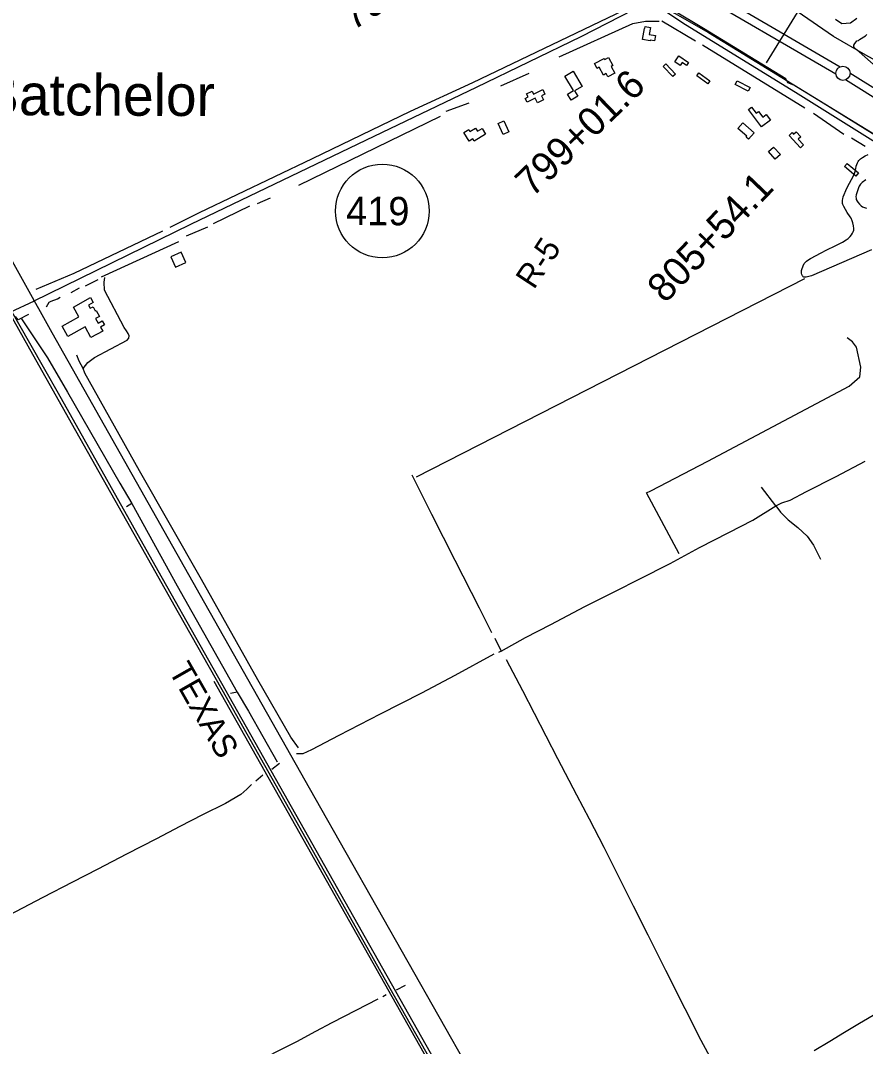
# Model space of a CAD drawing. Extents: x 3161514 to 3199414, y 831166 to 856601.
# Drawn here: x 3177957 to 3180931, y 848812 to 852425 of the extents above; entities that cross this region are included whole.
import ezdxf

# ---------------------------------------------------------------- set-up
doc = ezdxf.new("R2010")
doc.units = 0
for name, color, linetype in [('V-BLDG-OTLN', 7, 'Continuous'), ('V-LEVE-TOET', 7, 'Continuous'), ('V-RAIL-IDEN', 7, 'Continuous'), ('V-RAIL-TRAK', 7, 'Continuous'), ('V-RIVR-RANG-IDEN', 7, 'Continuous'), ('V-ROAD-CNTR', 7, 'Continuous'), ('V-ROAD-IDEN', 7, 'Continuous'), ('V-SITE-VEGE', 7, 'Continuous'), ('V-SURV-IDEN', 7, 'Continuous'), ('V-SURV-LINE', 7, 'Continuous'), ('V-TOPO-GNAM-IDEN', 7, 'Continuous'), ('V-TOPO-SHOR', 7, 'Continuous'), ('V-UTIL-LINE', 7, 'Continuous')]:
    doc.layers.add(name, color=color, linetype=linetype)

msp = doc.modelspace()

# ---------------------------------------------------------------- linework, layer by layer
at = {"layer": 'V-BLDG-OTLN'}
for points in [[(3180146.2, 852357.6), (3180152.6, 852397.3), (3180154.4, 852397.1), (3180155.5, 852403.9), (3180174, 852400.9), (3180169.9, 852375.6), (3180191.5, 852372.1), (3180188.5, 852353.4), (3180172.9, 852355.9), (3180172.5, 852353.4)], [(3180026.6, 852295), (3180041.5, 852266.3), (3180036.1, 852263.5), (3180048.7, 852239.3), (3180024, 852226.5), (3180018, 852238.2), (3180008, 852232.9), (3179993.6, 852260.4), (3179985.8, 852256.3), (3179976.6, 852274), (3180010.6, 852291.7), (3180012.7, 852287.8)], [(3180259.6, 852280.1), (3180274.2, 852301.1), (3180308.3, 852277.3), (3180300.5, 852266.1), (3180285, 852276.9), (3180278.2, 852267.1)], [(3180261.9, 852236.3), (3180252.2, 852227.3), (3180218.8, 852263.2), (3180228.5, 852272.3)], [(3179901.7, 852246.4), (3179933.1, 852193), (3179906.7, 852177.4), (3179918.1, 852158.1), (3179894.3, 852144.1), (3179881.6, 852165.7), (3179902.9, 852178.2), (3179872.8, 852229.4)], [(3180383.3, 852212.2), (3180375.9, 852202.2), (3180336.9, 852230.8), (3180344.2, 852240.8)], [(3179794.5, 852181.7), (3179802.3, 852166.2), (3179789.8, 852159.9), (3179797, 852145.6), (3179775.9, 852134.9), (3179767.7, 852151.2), (3179740, 852137.2), (3179733.1, 852150.9), (3179743.1, 852156), (3179737.7, 852166.8), (3179757.1, 852176.6), (3179762.7, 852165.6)], [(3180472.5, 852199.9), (3180479.3, 852212.9), (3180525, 852189.2), (3180518.2, 852176.2)], [(3180564.9, 852050.1), (3180518.6, 852111.7), (3180529.8, 852120.1), (3180545.8, 852098.7), (3180554.2, 852104.9), (3180569.3, 852084.9), (3180581.7, 852094.2), (3180596.8, 852074.1)], [(3179564.7, 852034.9), (3179581.3, 852045), (3179593.7, 852024.7), (3179553.7, 852000.3), (3179549, 852007.9), (3179535.9, 852000), (3179517.3, 852030.5), (3179534.5, 852041), (3179538.6, 852034.2), (3179557.9, 852046)], [(3179655.4, 852023.7), (3179638, 852062.8), (3179658.1, 852071.8), (3179675.5, 852032.7)], [(3180499.3, 852064.4), (3180539.1, 852029.4), (3180519.5, 852007.1), (3180511, 852014.6), (3180513.3, 852017.2), (3180482, 852044.8)], [(3180701.8, 851977), (3180662.2, 852020.2), (3180673.2, 852030.3), (3180677.7, 852025.3), (3180686.3, 852033.1), (3180702.8, 852015.1), (3180693.8, 852006.8), (3180712.3, 851986.7)], [(3180631.2, 851953.2), (3180613.4, 851937.1), (3180589.5, 851963.4), (3180607.3, 851979.6)], [(3180896.5, 851877), (3180856.9, 851910.4), (3180866.5, 851921.7), (3180906.1, 851888.3)], [(3178521.9, 851609.7), (3178485.4, 851593.4), (3178501.7, 851556.9), (3178538.2, 851573.2)], [(3178123.1, 851312.2), (3178102.6, 851349.2), (3178161.7, 851382.1), (3178143, 851415.9), (3178202.6, 851449.1), (3178212.2, 851431.7), (3178195.8, 851422.6), (3178201.9, 851411.7), (3178211.7, 851417.2), (3178219.8, 851402.8), (3178222.4, 851404.2), (3178234, 851383.3), (3178220.5, 851375.8), (3178229.4, 851359.7), (3178244.3, 851368), (3178252.5, 851353.2), (3178238.3, 851345.3), (3178245.9, 851331.6), (3178204.5, 851308.5), (3178183.7, 851345.9)]]:
    msp.add_lwpolyline(points, close=True, dxfattribs=at)
at = {"layer": 'V-LEVE-TOET'}
for points in [[(3180222.9, 852474.1), (3180225.4, 852472.2), (3180246, 852458.1), (3180261.2, 852449.3), (3180276.7, 852440.2), (3180378.3, 852382.9), (3180599.4, 852247.2), (3180781.4, 852135.7), (3180979.3, 852013.2)], [(3181272.1, 852116.2), (3181228.7, 852143.9), (3181064, 852230.7), (3180932, 852303.1), (3180817.6, 852369.1), (3180690.2, 852456.5), (3180643.2, 852490.5)]]:
    msp.add_lwpolyline(points, dxfattribs=at)
at = {"layer": 'V-RAIL-TRAK'}
msp.add_lwpolyline([(3179765, 848116.8), (3179728.2, 848182.9), (3179629.2, 848358.8), (3179423.1, 848723.5), (3179257.9, 849016.2), (3178929.8, 849600), (3178666.2, 850067.6), (3178513.1, 850338.6), (3178372, 850589.2), (3178150.9, 850980.6), (3177999.7, 851248.7), (3177917.5, 851395.3)], dxfattribs=at)
at = {"layer": 'V-ROAD-CNTR'}
for points in [[(3176113.1, 854794), (3176223.6, 854594.2), (3176701.4, 853750.7), (3177143.6, 852967.7), (3177688.4, 852004.2), (3178067, 851325.8), (3178604, 850374.6), (3178992.2, 849687.5), (3179538.6, 848724.8), (3179946.2, 848000.9), (3180424.9, 847143.9), (3180815.4, 846445.1), (3181367.5, 845470.9)], [(3177592.2, 854789.9), (3177971.4, 854316.2), (3178263.7, 853942.1), (3178396, 853775.7), (3178430.3, 853732.9), (3178457, 853704.8), (3178482.7, 853679.1), (3178527.4, 853641.6), (3178608, 853580.7), (3178927.2, 853358), (3179165.4, 853188.9), (3179528.5, 852937.7), (3180018.6, 852597.4), (3180287.5, 852417.1), (3180694.2, 852166.9), (3181125.4, 851896.4)], [(3176082.6, 854665.9), (3176267.3, 854340.9), (3176547.5, 853846.5), (3176830, 853348), (3177122.2, 852831.6), (3177540.4, 852086.9), (3177896.6, 851451.3), (3178089, 851112.6), (3178439.3, 850488.8), (3178766, 849911.1), (3179200, 849142.2), (3179692.7, 848269.2), (3179881.1, 847935.3), (3180257.6, 847259.5), (3180606, 846647.7), (3180852.5, 846213.2), (3181321, 845381)], [(3180170.3, 852495.6), (3180113.7, 852462.5), (3179929.1, 852368.1), (3179560.9, 852189.5), (3179173.1, 852003.7), (3178554.8, 851706.8), (3178001.4, 851435.4)], [(3180900.2, 852431.8), (3180877.8, 852415.9), (3180848, 852413.4), (3180825.4, 852428.5)], [(3178004.9, 851437.1), (3177919.3, 851396.5), (3177527.3, 851206.9), (3176975.4, 850941.8), (3176777.7, 850848.2), (3176154.2, 850545.1), (3175803.4, 850374.2), (3175245.4, 850104.3), (3174206.5, 849596.9)], [(3178636.8, 850098.4), (3179509.7, 848551), (3179761.1, 848112.3), (3179881.5, 847899.5), (3180304.8, 847141), (3180338, 847095.4), (3180383.2, 847039)]]:
    msp.add_lwpolyline(points, dxfattribs=at)
at = {"layer": 'V-ROAD-IDEN'}
msp.add_circle((3179230, 851754.1), 165, dxfattribs=at)
at = {"layer": 'V-SITE-VEGE'}
for points in [[(3180968.3, 852261.6), (3180909.1, 852315.1), (3180902.2, 852319.9), (3180894.9, 852325.7), (3180890.2, 852332.2), (3180889.3, 852335.6), (3180890.2, 852338.5), (3180893, 852344), (3180897.5, 852350.1), (3180900.8, 852353), (3180905.7, 852355), (3180909.4, 852357.9), (3180930.6, 852370.7), (3180935, 852376.2)], [(3180741, 851525.8), (3180721.8, 851521.8), (3180718, 851521.2), (3180714.2, 851521.5), (3180711.7, 851522.6), (3180709.8, 851524.2), (3180708.5, 851526), (3180707, 851530.3), (3180705.8, 851535.6), (3180705.3, 851540.9), (3180705.4, 851544.3), (3180706.3, 851548.8), (3180711.5, 851561.1), (3180715.5, 851568.9), (3180719.1, 851573.6), (3180723.4, 851577.7), (3180727.9, 851581.3), (3180737.5, 851587.4), (3180774.8, 851607.2), (3180792.1, 851615.9), (3180826.9, 851632.9), (3180849.8, 851644.9), (3180862.6, 851652.3), (3180866.4, 851654.8), (3180870, 851657.7), (3180876.6, 851664.3), (3180881.4, 851670.2), (3180885.4, 851676.6), (3180887.8, 851681.3), (3180889.8, 851686.8), (3180890.3, 851692.2), (3180889.1, 851702.5), (3180886.5, 851712.8), (3180884.1, 851719.6), (3180879.8, 851728.5), (3180876.6, 851733.8), (3180866.5, 851748.7), (3180860.1, 851759.2), (3180854.4, 851770), (3180851.3, 851777.3), (3180850.3, 851780.8), (3180849.8, 851784.4), (3180850, 851791.9), (3180850.8, 851797), (3180852.6, 851803.7), (3180855.6, 851812.3), (3180861.4, 851825.9), (3180868, 851839.1), (3180882.1, 851865.2), (3180890.6, 851882.9), (3180894.6, 851893.2), (3180896.8, 851902.6), (3180898.4, 851912.3), (3180900.1, 851918.5), (3180902.3, 851923.8), (3180905.2, 851928.7), (3180907.6, 851931.8), (3180913.5, 851937.6), (3180920.2, 851942.6), (3180929.7, 851948.4), (3180939.8, 851953.1)], [(3180931.7, 851864.3), (3180919.5, 851854.9), (3180916.3, 851851.9), (3180913.5, 851848.6), (3180908.8, 851841.3), (3180906.3, 851836), (3180903.4, 851828.7), (3180899.8, 851818.6), (3180897.9, 851811.6), (3180897.2, 851804.6), (3180897.4, 851800), (3180898.5, 851794.2), (3180901, 851788.6), (3180903.3, 851784.9), (3180909.3, 851777.9), (3180915.7, 851772.4), (3180920.5, 851769.4), (3180927.4, 851766.4), (3180934.7, 851764.5)], [(3180952.2, 851617.1), (3180882.1, 851586.4), (3180741, 851525.8)]]:
    msp.add_lwpolyline(points, dxfattribs=at)
at = {"layer": 'V-SURV-LINE'}
for points in [[(3180826.5, 852236.3), (3180297.5, 852545.4)], [(3180312.7, 852571.3), (3180841.6, 852262.2)], [(3180876.2, 852241.3), (3181733.3, 851705.6)], [(3181717.4, 851680.2), (3180860.3, 852215.9)]]:
    msp.add_lwpolyline(points, dxfattribs=at)
msp.add_circle((3180851.3, 852239.2), 25, dxfattribs=at)
at = {"layer": 'V-TOPO-SHOR'}
for p, q in [((3180332.9, 852351.8), (3180214, 852422.4)), ((3180717.5, 852115.9), (3180357.1, 852338.8)), ((3179646.9, 852194.9), (3179746.5, 852239.1)), ((3179454.4, 852106.3), (3179536.3, 852135.1)), ((3178936.5, 851845.2), (3179434.5, 852088.6)), ((3180747.2, 852099.2), (3180855, 852024.8)), ((3180881, 852011.8), (3180929.3, 851982.1)), ((3178790.4, 851781), (3178836.9, 851800.9)), ((3178635.5, 851710.2), (3178763.9, 851772.1)), ((3178540.5, 851667), (3178616.3, 851698.7)), ((3178241.7, 851522), (3178513.2, 851647)), ((3178185.4, 851490.7), (3178229.5, 851512.6)), ((3179350, 850817.6), (3180717.5, 851516.2)), ((3178134.2, 851467), (3178164.1, 851483.6)), ((3180614.9, 850715.4), (3180564.5, 850781.4)), ((3179625.6, 850250.2), (3179648.2, 850204.4)), ((3179648.2, 850204.4), (3179639.3, 850199.3)), ((3178868.1, 849809.1), (3178841.2, 849787.8)), ((3178809, 849768.1), (3178785, 849746.8)), ((3179310.8, 849026.6), (3179278.9, 849010.9)), ((3179243.2, 848993.8), (3179231.5, 848986.5))]:
    msp.add_line(p, q, dxfattribs=at)
for points in [[(3178697.5, 853498.4), (3178945.3, 853325.8), (3179452.2, 852967.3), (3179757.6, 852754.8), (3180091.8, 852515.8), (3180105.1, 852491.4), (3180096.2, 852475.9), (3180078.5, 852460.5), (3179547.3, 852205.9), (3179328.2, 852104.1), (3178983.4, 851938.3)], [(3180985, 852010), (3180678.5, 852197.6), (3180658, 852205.1), (3180650.6, 852219.9), (3180360.8, 852396.4), (3180253, 852461.5), (3180254.9, 852467), (3180262.3, 852470.7)], [(3179852.8, 852296.7), (3180111.7, 852414), (3180156, 852422.8), (3180193.6, 852422.8), (3180204.7, 852422.8)], [(3178983.4, 851938.3), (3178585.6, 851748.3), (3178481.5, 851696.4)], [(3178456.3, 851683.4), (3178143.7, 851534.2), (3178010.2, 851477.3)], [(3178177.4, 851199.2), (3178194, 851220.2), (3178217.2, 851237.9), (3178332.3, 851298.8), (3178337.8, 851306.5), (3178338.9, 851314.3), (3178335.6, 851323.1), (3178330.1, 851332), (3178321.2, 851344.2), (3178252.6, 851475.9), (3178251.5, 851503.5), (3178253.7, 851520.1)], [(3178047.9, 851417.2), (3178057.9, 851432.7), (3178064.5, 851437.1), (3178086.6, 851444.9), (3178096.6, 851450.4)], [(3177984.8, 851389.5), (3177948.3, 851370.7), (3177939.4, 851382.9)], [(3177960.5, 851374), (3178051.2, 851236.8), (3178122, 851116.2), (3178305.7, 850795.3), (3178347.8, 850724.5), (3178330.1, 850712.3)], [(3180275.3, 850546.4), (3180160.1, 850761.9), (3180175, 850769.3), (3180375.6, 850873.4), (3180873.6, 851137.2), (3180910.7, 851170.6), (3180914.4, 851204.1), (3180899.6, 851274.7), (3180884.7, 851293.3), (3180866.1, 851308.1)], [(3178935.4, 849863.5), (3178907.7, 849901.2), (3178791.5, 850103.7), (3178593.4, 850456.7), (3178375.4, 850839.6), (3178182.9, 851182.6), (3178177.4, 851199.2), (3178163, 851225.8), (3178155.2, 851246.8)], [(3180614.9, 850715.4), (3180636.4, 850726.6), (3180665.7, 850736.1), (3180722.8, 850766.2), (3180827.1, 850819.8), (3180929.5, 850873.4)], [(3179333.9, 850825.4), (3179403, 850686.2), (3179484.9, 850525.1), (3179570.9, 850356.7), (3179614.5, 850270.4)], [(3178347.8, 850724.5), (3178508.2, 850434.5), (3178719.6, 850059.4), (3178695.3, 850055)], [(3179648.2, 850204.4), (3179733.9, 850252.1), (3179823.7, 850298.6), (3179942.8, 850361.2), (3180050.4, 850415.6), (3180134.7, 850458.1), (3180243, 850513.2), (3180346.5, 850569.5), (3180450.3, 850622.2), (3180533.8, 850665.3), (3180614.9, 850715.4)], [(3180614.9, 850715.4), (3180631.3, 850693.4), (3180659, 850667.2), (3180693.1, 850640), (3180725.4, 850609.5), (3180747.5, 850577), (3180772.3, 850528)], [(3179622.5, 850193.4), (3179485.2, 850118), (3179367.5, 850056.6), (3179222.7, 849982.2), (3179076.7, 849907.2), (3178980.7, 849856.8), (3178949.9, 849842.9), (3178928.3, 849842.3)], [(3180464.3, 848628), (3180421.2, 848705.6), (3180351.8, 848833.5), (3180295.5, 848945.2), (3180227.7, 849080.1), (3180165.4, 849204.5), (3180114.1, 849305.7), (3180061.2, 849412), (3180010.7, 849512.5), (3179959.4, 849612.5), (3179914.6, 849697.3), (3179847.8, 849824.8), (3179724.3, 850064.9), (3179666.9, 850174.1)], [(3178719.6, 850059.4), (3178759.4, 849993), (3178860.1, 849814.9)], [(3178770, 849734.9), (3178753.6, 849717.7), (3178732, 849699.4), (3178678.1, 849667.5), (3178596.8, 849627.4), (3178517.4, 849587), (3178434.8, 849543.2), (3178329.9, 849489.4), (3178228.7, 849436.6), (3178139.6, 849391.1), (3178034.9, 849336.2), (3177938.8, 849286.5), (3177838, 849236), (3177754.2, 849193.1), (3177638.4, 849127.9), (3177553.2, 849085.1), (3177440.6, 849027.8), (3177340, 848973.1), (3177224.2, 848916.1), (3177136.6, 848870.3), (3177100.3, 848851.6), (3177077, 848839.3)], [(3179214.6, 848978.4), (3179137, 848939.2), (3179052.4, 848894.8), (3178995.3, 848865.1), (3178927.4, 848828), (3178850.6, 848789.6), (3178776.3, 848748.8), (3178706.7, 848712.6), (3178630.1, 848671.3), (3178526.5, 848619.2)], [(3180971.3, 848929.1), (3180909.8, 848893.4), (3180857, 848860.8), (3180805.3, 848829.4), (3180750.5, 848796.7)]]:
    msp.add_lwpolyline(points, dxfattribs=at)
at = {"layer": 'V-UTIL-LINE'}
msp.add_line((3180582.5, 852275.5), (3180691.6, 852453.7), dxfattribs=at)

# ---------------------------------------------------------------- texts
at = {"layer": 'V-RAIL-IDEN'}
msp.add_text('TEXAS', height=83, rotation=299.6851, dxfattribs=at).set_placement((3178475.9, 850135.4))
at = {"layer": 'V-RIVR-RANG-IDEN'}
msp.add_text('R-5', height=83, rotation=56.57, dxfattribs=at).set_placement((3179763.6, 851474.7))
at = {"layer": 'V-ROAD-IDEN'}
msp.add_text('419', height=100, rotation=359.7334, dxfattribs=at).set_placement((3179102.2, 851704.7))
at = {"layer": 'V-SURV-IDEN'}
for s, rotation, p in [('792+90.0', 32.6387, (3179126.2, 852388)), ('799+01.6', 43.8666, (3179757.6, 851799.6)), ('805+54.1', 46.3418, (3180225.6, 851426.1))]:
    msp.add_text(s, height=100, rotation=rotation, dxfattribs=at).set_placement(p)
at = {"layer": 'V-TOPO-GNAM-IDEN'}
msp.add_text('Batchelor', height=145, rotation=359.7335, dxfattribs=at).set_placement((3177821.3, 852092.2))

doc.saveas('drawing.dxf')
